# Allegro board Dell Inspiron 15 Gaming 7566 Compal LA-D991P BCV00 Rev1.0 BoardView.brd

Outline 310.04 x 134.8 mm; copper layers: TOP, GND1, IN1, VCC, IN2, IN3, GND2, BOTTOM. Coordinates in mm from the lower left corner of the outline.

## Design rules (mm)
constraint set DEFAULT: min track width 0.102
net group 90H_5.4/8/6.5/6.5/5.4: nets XTAL_OUT XTALIN
net group CLK_PEG_N16P: nets CLK_PEG_N16P CLK_PEG_N16P#
net group CPU_24MHZ_P: nets CPU_24MHZ_N CPU_24MHZ_P
net group DDC_CLK_HDMI: nets DDC_CLK_HDMI DDC_DAT_HDMI
net group DIFFPAIR0: nets VCCSENSE_VGA VSSSENSE_VGA
net group DIFFPAIR1: nets VCCSA_SENSE VSSSA_SENSE
net group DMI_CRX_PTX_0: nets DMI_CRX_PTX_N0 DMI_CRX_PTX_P0
net group DMI_CRX_PTX_1: nets DMI_CRX_PTX_N1 DMI_CRX_PTX_P1
net group DMI_CRX_PTX_2: nets DMI_CRX_PTX_N2 DMI_CRX_PTX_P2
net group DMI_CRX_PTX_3: nets DMI_CRX_PTX_N3 DMI_CRX_PTX_P3
net group DMI_CTX_PRX_0: nets DMI_CTX_PRX_N0 DMI_CTX_PRX_P0
net group DMI_CTX_PRX_1: nets DMI_CTX_PRX_N1 DMI_CTX_PRX_P1
net group DMI_CTX_PRX_2: nets DMI_CTX_PRX_N2 DMI_CTX_PRX_P2
net group DMI_CTX_PRX_3: nets DMI_CTX_PRX_N3 DMI_CTX_PRX_P3
net group DP1: nets N123984002 N123984213
net group DP2: nets N123984081 N123985122
net group DP3: nets N57527 V3N
net group DP4: nets N122477585 V2N
net group DP5: nets N122476680 V1N
net group DP6: nets ISUMN_SA ISUMP_SA
net group DP7: nets VCCIO_SENSE VSSIO_SENSE
net group EDP_AUX: nets EDP_AUXN EDP_AUXP
net group EDP_AUX_C: nets EDP_AUXN_C EDP_AUXP_C
net group EDP_AUX_R: nets EDP_AUXN_R EDP_AUXP_R
net group EDP_TX0: nets EDP_TXN0 EDP_TXP0
net group EDP_TX0_C: nets EDP_TXN0_C EDP_TXP0_C
net group EDP_TX0_R: nets EDP_TXN0_R EDP_TXP0_R
net group EDP_TX1: nets EDP_TXN1 EDP_TXP1
net group EDP_TX1_C: nets EDP_TXN1_C EDP_TXP1_C
net group EDP_TX1_R: nets EDP_TXN1_R EDP_TXP1_R
net group EDP_TX2: nets EDP_TXN2 EDP_TXP2
net group EDP_TX2_C: nets EDP_TXN2_C EDP_TXP2_C
net group EDP_TX2_R: nets EDP_TXN2_R EDP_TXP2_R
net group EDP_TX3: nets EDP_TXN3 EDP_TXP3
net group EDP_TX3_C: nets EDP_TXN3_C EDP_TXP3_C
net group EDP_TX3_R: nets EDP_TXN3_R EDP_TXP3_R
net group FBA_CLK0: nets FBA_CLK0 FBA_CLK0#
net group FBA_CLK1: nets FBA_CLK1 FBA_CLK1#
net group FBA_WCK0: nets FBA_WCK0 FBA_WCK0_N
net group FBA_WCK1: nets FBA_WCK1 FBA_WCK1_N
net group FBA_WCK2: nets FBA_WCK2 FBA_WCK2_N
net group FBA_WCK3: nets FBA_WCK3 FBA_WCK3_N
net group FBC_CLK0: nets FBC_CLK0 FBC_CLK0#
net group FBC_CLK1: nets FBC_CLK1 FBC_CLK1#
net group FBC_WCK0: nets FBC_WCK0 FBC_WCK0_N
net group FBC_WCK1: nets FBC_WCK1 FBC_WCK1_N
net group FBC_WCK2: nets FBC_WCK2 FBC_WCK2_N
net group FBC_WCK3: nets FBC_WCK3 FBC_WCK3_N
net group PBAT_CHG_SMB: nets PBAT_CHG_SMBCLK PBAT_CHG_SMBDAT
net group PCH_CPU_PCIBCLK_: nets PCH_CPU_PCIBCLK_N PCH_CPU_PCIBCLK_P
net group PCIE_PRX_LANTX_3_C: nets PCIE_PRX_LANTX_N3_C PCIE_PRX_LANTX_P3_C
net group PCIE_PRX_LANTX_5: nets PCIE_PRX_LANTX_N5 PCIE_PRX_LANTX_P5
net group PCIE_PRX_SSDTX_10: nets PCIE_PRX_SSDTX_N10 PCIE_PRX_SSDTX_P10
net group PCIE_PRX_SSDTX_11: nets PCIE_PRX_SSDTX_N11 PCIE_PRX_SSDTX_P11
net group PCIE_PRX_SSDTX_12: nets PCIE_PRX_SSDTX_N12 PCIE_PRX_SSDTX_P12
net group PCIE_PRX_WLANTX_6: nets PCIE_PRX_WLANTX_N6 PCIE_PRX_WLANTX_P6
net group PCIE_PTX_LANRX_N5: nets PCIE_PTX_LANRX_N5 PCIE_PTX_LANRX_N5_C
net group PCIE_PTX_LANRX_P5: nets PCIE_PTX_LANRX_P5 PCIE_PTX_LANRX_P5_C
net group PCIE_PTX_SSDRX_10: nets PCIE_PTX_SSDRX_N10 PCIE_PTX_SSDRX_P10
net group PCIE_PTX_SSDRX_10_C: nets PCIE_PTX_SSDRX_N10_C PCIE_PTX_SSDRX_P10_C
net group PCIE_PTX_SSDRX_11: nets PCIE_PTX_SSDRX_N11 PCIE_PTX_SSDRX_P11
net group PCIE_PTX_SSDRX_11_C: nets PCIE_PTX_SSDRX_N11_C PCIE_PTX_SSDRX_P11_C
net group PCIE_PTX_SSDRX_12: nets PCIE_PTX_SSDRX_N12 PCIE_PTX_SSDRX_P12
net group PCIE_PTX_SSDRX_12_C: nets PCIE_PTX_SSDRX_N12_C PCIE_PTX_SSDRX_P12_C
net group PCIE_PTX_WLANRX_6: nets PCIE_PTX_WLANRX_N6 PCIE_PTX_WLANRX_P6
net group PCIE_PTX_WLANRX_RE_6: nets PCIE_PTX_WLANRX_RE_N6 PCIE_PTX_WLANRX_RE_P6
net group PEG_GTX_C_HRX_0: nets PEG_GTX_C_HRX_N0 PEG_GTX_C_HRX_P0
net group PEG_GTX_C_HRX_1: nets PEG_GTX_C_HRX_N1 PEG_GTX_C_HRX_P1
net group PEG_GTX_C_HRX_2: nets PEG_GTX_C_HRX_N2 PEG_GTX_C_HRX_P2
net group PEG_GTX_C_HRX_3: nets PEG_GTX_C_HRX_N3 PEG_GTX_C_HRX_P3
net group PEG_GTX_C_HRX_4: nets PEG_GTX_C_HRX_N4 PEG_GTX_C_HRX_P4
net group PEG_GTX_C_HRX_5: nets PEG_GTX_C_HRX_N5 PEG_GTX_C_HRX_P5
net group PEG_GTX_C_HRX_6: nets PEG_GTX_C_HRX_N6 PEG_GTX_C_HRX_P6
net group PEG_GTX_C_HRX_7: nets PEG_GTX_C_HRX_N7 PEG_GTX_C_HRX_P7
net group PEG_GTX_C_HRX_8: nets PEG_GTX_C_HRX_N8 PEG_GTX_C_HRX_P8
net group PEG_GTX_C_HRX_9: nets PEG_GTX_C_HRX_N9 PEG_GTX_C_HRX_P9
net group PEG_GTX_C_HRX_10: nets PEG_GTX_C_HRX_N10 PEG_GTX_C_HRX_P10
net group PEG_GTX_C_HRX_11: nets PEG_GTX_C_HRX_N11 PEG_GTX_C_HRX_P11
net group PEG_GTX_C_HRX_12: nets PEG_GTX_C_HRX_N12 PEG_GTX_C_HRX_P12
net group PEG_GTX_C_HRX_13: nets PEG_GTX_C_HRX_N13 PEG_GTX_C_HRX_P13
net group PEG_GTX_C_HRX_14: nets PEG_GTX_C_HRX_N14 PEG_GTX_C_HRX_P14
net group PEG_GTX_C_HRX_15: nets PEG_GTX_C_HRX_N15 PEG_GTX_C_HRX_P15
net group PEG_GTX_HRX_0: nets PEG_GTX_HRX_N0 PEG_GTX_HRX_P0
net group PEG_GTX_HRX_1: nets PEG_GTX_HRX_N1 PEG_GTX_HRX_P1
net group PEG_GTX_HRX_2: nets PEG_GTX_HRX_N2 PEG_GTX_HRX_P2
net group PEG_GTX_HRX_3: nets PEG_GTX_HRX_N3 PEG_GTX_HRX_P3
net group PEG_GTX_HRX_4: nets PEG_GTX_HRX_N4 PEG_GTX_HRX_P4
net group PEG_GTX_HRX_5: nets PEG_GTX_HRX_N5 PEG_GTX_HRX_P5
net group PEG_GTX_HRX_6: nets PEG_GTX_HRX_N6 PEG_GTX_HRX_P6
net group PEG_GTX_HRX_7: nets PEG_GTX_HRX_N7 PEG_GTX_HRX_P7
net group PEG_GTX_HRX_8: nets PEG_GTX_HRX_N8 PEG_GTX_HRX_P8
net group PEG_GTX_HRX_9: nets PEG_GTX_HRX_N9 PEG_GTX_HRX_P9
net group PEG_GTX_HRX_10: nets PEG_GTX_HRX_N10 PEG_GTX_HRX_P10
net group PEG_GTX_HRX_11: nets PEG_GTX_HRX_N11 PEG_GTX_HRX_P11
net group PEG_GTX_HRX_12: nets PEG_GTX_HRX_N12 PEG_GTX_HRX_P12
net group PEG_GTX_HRX_13: nets PEG_GTX_HRX_N13 PEG_GTX_HRX_P13
net group PEG_GTX_HRX_14: nets PEG_GTX_HRX_N14 PEG_GTX_HRX_P14
net group PEG_GTX_HRX_15: nets PEG_GTX_HRX_N15 PEG_GTX_HRX_P15
net group PEG_HTX_C_GRX_0: nets PEG_HTX_C_GRX_N0 PEG_HTX_C_GRX_P0
net group PEG_HTX_C_GRX_1: nets PEG_HTX_C_GRX_N1 PEG_HTX_C_GRX_P1
net group PEG_HTX_C_GRX_2: nets PEG_HTX_C_GRX_N2 PEG_HTX_C_GRX_P2
net group PEG_HTX_C_GRX_3: nets PEG_HTX_C_GRX_N3 PEG_HTX_C_GRX_P3
net group PEG_HTX_C_GRX_4: nets PEG_HTX_C_GRX_N4 PEG_HTX_C_GRX_P4
net group PEG_HTX_C_GRX_5: nets PEG_HTX_C_GRX_N5 PEG_HTX_C_GRX_P5
net group PEG_HTX_C_GRX_6: nets PEG_HTX_C_GRX_N6 PEG_HTX_C_GRX_P6
net group PEG_HTX_C_GRX_7: nets PEG_HTX_C_GRX_N7 PEG_HTX_C_GRX_P7
net group PEG_HTX_C_GRX_8: nets PEG_HTX_C_GRX_N8 PEG_HTX_C_GRX_P8
net group PEG_HTX_C_GRX_9: nets PEG_HTX_C_GRX_N9 PEG_HTX_C_GRX_P9
net group PEG_HTX_C_GRX_10: nets PEG_HTX_C_GRX_N10 PEG_HTX_C_GRX_P10
net group PEG_HTX_C_GRX_11: nets PEG_HTX_C_GRX_N11 PEG_HTX_C_GRX_P11
net group PEG_HTX_C_GRX_12: nets PEG_HTX_C_GRX_N12 PEG_HTX_C_GRX_P12
net group PEG_HTX_C_GRX_13: nets PEG_HTX_C_GRX_N13 PEG_HTX_C_GRX_P13
net group PEG_HTX_C_GRX_14: nets PEG_HTX_C_GRX_N14 PEG_HTX_C_GRX_P14
net group PEG_HTX_C_GRX_15: nets PEG_HTX_C_GRX_N15 PEG_HTX_C_GRX_P15
net group PEG_HTX_GRX_0: nets PEG_HTX_GRX_N0 PEG_HTX_GRX_P0
net group PEG_HTX_GRX_1: nets PEG_HTX_GRX_N1 PEG_HTX_GRX_P1
net group PEG_HTX_GRX_2: nets PEG_HTX_GRX_N2 PEG_HTX_GRX_P2
net group PEG_HTX_GRX_3: nets PEG_HTX_GRX_N3 PEG_HTX_GRX_P3
net group PEG_HTX_GRX_4: nets PEG_HTX_GRX_N4 PEG_HTX_GRX_P4
net group PEG_HTX_GRX_5: nets PEG_HTX_GRX_N5 PEG_HTX_GRX_P5
net group PEG_HTX_GRX_6: nets PEG_HTX_GRX_N6 PEG_HTX_GRX_P6
net group PEG_HTX_GRX_7: nets PEG_HTX_GRX_N7 PEG_HTX_GRX_P7
net group PEG_HTX_GRX_8: nets PEG_HTX_GRX_N8 PEG_HTX_GRX_P8
net group PEG_HTX_GRX_9: nets PEG_HTX_GRX_N9 PEG_HTX_GRX_P9
net group PEG_HTX_GRX_10: nets PEG_HTX_GRX_N10 PEG_HTX_GRX_P10
net group PEG_HTX_GRX_11: nets PEG_HTX_GRX_N11 PEG_HTX_GRX_P11
net group PEG_HTX_GRX_12: nets PEG_HTX_GRX_N12 PEG_HTX_GRX_P12
net group PEG_HTX_GRX_13: nets PEG_HTX_GRX_N13 PEG_HTX_GRX_P13
net group PEG_HTX_GRX_14: nets PEG_HTX_GRX_N14 PEG_HTX_GRX_P14
net group PEG_HTX_GRX_15: nets PEG_HTX_GRX_N15 PEG_HTX_GRX_P15
net group REMOTE1: nets REMOTE1+ REMOTE1-
net group REMOTE2: nets REMOTE2+ REMOTE2-
net group SATA_PRX_DTX_1B: nets SATA_PRX_DTX_N1B SATA_PRX_DTX_P1B
net group SATA_PRX_DTX_1B_RC: nets SATA_PRX_DTX_N1B_RC SATA_PRX_DTX_P1B_RC
net group SATA_PRX_SSDTX_0A: nets SATA_PRX_SSDTX_N0A SATA_PRX_SSDTX_P0A
net group SATA_PTX_DRX_1B: nets SATA_PTX_DRX_N1B SATA_PTX_DRX_P1B
net group SATA_PTX_DRX_1B_RC: nets SATA_PTX_DRX_N1B_RC SATA_PTX_DRX_P1B_RC
net group SATA_PTX_SSDRX_0A: nets SATA_PTX_SSDRX_N0A SATA_PTX_SSDRX_P0A
net group SATA_PTX_SSDRX_0A_C: nets SATA_PTX_SSDRX_N0A_C SATA_PTX_SSDRX_P0A_C
net group SMBUS: nets DDI1_DDPB_CTRLDAT I2CB_SDA
net group TMDS_T_TX0P: nets TMDS_T_TX0N TMDS_T_TX0P
net group TMDS_T_TX1P: nets TMDS_T_TX1N TMDS_T_TX1P
net group TMDS_T_TX2P: nets TMDS_T_TX2N TMDS_T_TX2P
net group TMDS_T_TXCP: nets TMDS_T_TXCN TMDS_T_TXCP
net group USB3RN1_D: nets USB3RN1_D- USB3RP1_D+
net group USB3RN2_D: nets USB3RN2_D- USB3RP2_D+
net group USB3T_1: nets USB3T_N1 USB3T_P1
net group USB3T_2: nets USB3T_N2 USB3T_P2
net group USB3TN2_D: nets USB3TN2_D- USB3TP2_D+
net group USB3TP1_D: nets USB3TN1_D- USB3TP1_D+
net group USB20_P3: nets USB20_N3 USB20_P3
net group USB20_P4: nets USB20_N4 USB20_P4
net group USB20_P4_R: nets USB20_N4_R USB20_P4_R
net group USB20_P7: nets USB20_N7 USB20_P7
net group USB20_P9: nets USB20_N9 USB20_P9
net group USB20_P9_R: nets USB20_N9_R USB20_P9_R
net group USB20_P12: nets USB20_N12 USB20_P12
net group USB20_P12_R: nets USB20_N12_R USB20_P12_R
net group XDP: nets XDP_PRDY# XDP_PREQ#
net group 12: nets EC_SPI_CS# EC_SPI_CS#_R EC_SPI_SI EC_SPI_SI_R EC_SPI_SO EC_SPI_SO_R PCH_SPI_HOLD# PCH_SPI_HOLD#_R PCH_SPI_SI PCH_SPI_SI_R PCH_SPI_SO PCH_SPI_SO_R PCH_SPI_WP# PCH_SPI_WP#_R
net group 15: nets HDA_BITCLK HDA_BITCLK_AUDIO USB2_COMP
net group 20: nets DDI1_DDPB_CTRLCLK EC_SPI_CLK EC_SPI_CLK_R GPU_THM_SMBCLK I2C0_SCK I2C1_SCK_TP I2C1_SCK_TP_C I2CB_SCL N120361079 PCH_SMBCLK PCH_SPI_CLK PCH_SPI_CLK_R SMBCLK SML0_SMBCLK SML1_SMBCLK SUSCLK SUSCLK_R VGA_SMB_CK2
net group ASYNCHRONOUS: nets CFG_RCOMP DGPU_HOLD_RST# EDP_COMP H_CATERR# H_CPUPWRGD H_PROCHOT# H_PROCHOT#_R H_THERMTRIP# ME_SUS_PWR_ACK PCH_DPWROK PCH_PLTRST# PCH_PWROK PCH_RSMRST#_R PCH_RTCRST# SYS_PWROK SYS_RESET#
net group CLK_PCIE_SSD: nets CLK_PCIE_SSD
net group CODEC: nets RING2_R
net group DDRA_CLK: nets DDR_A_DQS0 DDR_A_DQS1 DDR_A_DQS2 DDR_A_DQS3 DDR_A_DQS4 DDR_A_DQS5 DDR_A_DQS6 DDR_A_DQS7 M_CLK_DDR0 M_CLK_DDR1 M_CLK_DDR#0 M_CLK_DDR#1
net group DDRA_CMD: nets DDR_A_ACT# DDR_A_ALERT# DDR_A_BG0 DDR_A_BG1 DDR_A_BS0 DDR_A_BS1 DDR_A_CAS# DDR_A_MA0 DDR_A_MA1 DDR_A_MA2 DDR_A_MA3 DDR_A_MA4 DDR_A_MA5 DDR_A_MA6 DDR_A_MA7 DDR_A_MA8 DDR_A_MA9 DDR_A_MA10 DDR_A_MA11 DDR_A_MA12 DDR_A_MA13 DDR_A_PAR DDR_A_RAS# DDR_A_WE#
net group DDRA_CTL: nets DDR_CKE0_DIMMA DDR_CKE1_DIMMA DDR_CS0_DIMMA# DDR_CS1_DIMMA# M_ODT0 M_ODT1
net group DDRA_D0: nets DDR_A_D0 DDR_A_D1 DDR_A_D2 DDR_A_D3 DDR_A_D4 DDR_A_D5 DDR_A_D6 DDR_A_D7 DDR_A_DQS#0
net group DDRA_D1: nets DDR_A_D8 DDR_A_D9 DDR_A_D10 DDR_A_D11 DDR_A_D12 DDR_A_D13 DDR_A_D14 DDR_A_D15 DDR_A_DQS#1
net group DDRA_D2: nets DDR_A_D16 DDR_A_D17 DDR_A_D18 DDR_A_D19 DDR_A_D20 DDR_A_D21 DDR_A_D22 DDR_A_D23 DDR_A_DQS#2
net group DDRA_D3: nets DDR_A_D24 DDR_A_D25 DDR_A_D26 DDR_A_D27 DDR_A_D28 DDR_A_D29 DDR_A_D30 DDR_A_D31 DDR_A_DQS#3
net group DDRA_D4: nets DDR_A_D32 DDR_A_D33 DDR_A_D34 DDR_A_D35 DDR_A_D36 DDR_A_D37 DDR_A_D38 DDR_A_D39 DDR_A_DQS#4
net group DDRA_D5: nets DDR_A_D40 DDR_A_D41 DDR_A_D42 DDR_A_D43 DDR_A_D44 DDR_A_D45 DDR_A_D46 DDR_A_D47 DDR_A_DQS#5
net group DDRA_D6: nets DDR_A_D48 DDR_A_D49 DDR_A_D50 DDR_A_D51 DDR_A_D52 DDR_A_D53 DDR_A_D54 DDR_A_D55 DDR_A_DQS#6
net group DDRA_D7: nets DDR_A_D56 DDR_A_D57 DDR_A_D58 DDR_A_D59 DDR_A_D60 DDR_A_D61 DDR_A_D62 DDR_A_D63 DDR_A_DQS#7
net group DDRB_CLK: nets DDR_B_DQS0 DDR_B_DQS1 DDR_B_DQS2 DDR_B_DQS3 DDR_B_DQS4 DDR_B_DQS5 DDR_B_DQS6 DDR_B_DQS7 M_CLK_DDR2 M_CLK_DDR3 M_CLK_DDR#2 M_CLK_DDR#3
net group DDRB_CMD: nets DDR_B_ACT# DDR_B_ALERT# DDR_B_BG0 DDR_B_BG1 DDR_B_BS0 DDR_B_BS1 DDR_B_CAS# DDR_B_MA0 DDR_B_MA1 DDR_B_MA2 DDR_B_MA3 DDR_B_MA4 DDR_B_MA5 DDR_B_MA6 DDR_B_MA7 DDR_B_MA8 DDR_B_MA9 DDR_B_MA10 DDR_B_MA11 DDR_B_MA12 DDR_B_MA13 DDR_B_PAR DDR_B_RAS# DDR_B_WE#
net group DDRB_CTL: nets DDR_CKE2_DIMMB DDR_CKE3_DIMMB DDR_CS2_DIMMB# DDR_CS3_DIMMB# M_ODT2 M_ODT3
net group DDRB_D0: nets DDR_B_D0 DDR_B_D1 DDR_B_D2 DDR_B_D3 DDR_B_D4 DDR_B_D5 DDR_B_D6 DDR_B_D7 DDR_B_DQS#0
net group DDRB_D1: nets DDR_B_D8 DDR_B_D9 DDR_B_D10 DDR_B_D11 DDR_B_D12 DDR_B_D13 DDR_B_D14 DDR_B_D15 DDR_B_DQS#1
net group DDRB_D2: nets DDR_B_D16 DDR_B_D17 DDR_B_D18 DDR_B_D19 DDR_B_D20 DDR_B_D21 DDR_B_D22 DDR_B_D23 DDR_B_DQS#2
net group DDRB_D3: nets DDR_B_D24 DDR_B_D25 DDR_B_D26 DDR_B_D27 DDR_B_D28 DDR_B_D29 DDR_B_D30 DDR_B_D31 DDR_B_DQS#3
net group DDRB_D4: nets DDR_B_D32 DDR_B_D33 DDR_B_D34 DDR_B_D35 DDR_B_D36 DDR_B_D37 DDR_B_D38 DDR_B_D39 DDR_B_DQS#4
net group DDRB_D5: nets DDR_B_D40 DDR_B_D41 DDR_B_D42 DDR_B_D43 DDR_B_D44 DDR_B_D45 DDR_B_D46 DDR_B_D47 DDR_B_DQS#5
net group DDRB_D6: nets DDR_B_D48 DDR_B_D49 DDR_B_D50 DDR_B_D51 DDR_B_D52 DDR_B_D53 DDR_B_D54 DDR_B_D55 DDR_B_DQS#6
net group DDRB_D7: nets DDR_B_D56 DDR_B_D57 DDR_B_D58 DDR_B_D59 DDR_B_D60 DDR_B_D61 DDR_B_D62 DDR_B_D63 DDR_B_DQS#7
net group DP: nets DDI1_CPU_AUXN DDI1_CPU_AUXN_C DDI1_CPU_AUXP DDI1_CPU_AUXP_C DDI1_HTX_TBRX_N0 DDI1_HTX_TBRX_N0_C DDI1_HTX_TBRX_N1 DDI1_HTX_TBRX_N1_C DDI1_HTX_TBRX_N2 DDI1_HTX_TBRX_N2_C DDI1_HTX_TBRX_N3 DDI1_HTX_TBRX_N3_C DDI1_HTX_TBRX_P0 DDI1_HTX_TBRX_P0_C DDI1_HTX_TBRX_P1 DDI1_HTX_TBRX_P1_C DDI1_HTX_TBRX_P2 DDI1_HTX_TBRX_P2_C DDI1_HTX_TBRX_P3 DDI1_HTX_TBRX_P3_C
net group FBA_CMD: nets FBA_ABI#_H FBA_ABI#_L FBA_CAS#_H FBA_CAS#_L FBA_CKE_H FBA_CKE_L FBA_CS#_H FBA_CS#_L FBA_MA0_MA10_H FBA_MA0_MA10_L FBA_MA1_MA9_H FBA_MA1_MA9_L FBA_MA2_BA0_H FBA_MA2_BA0_L FBA_MA3_BA3_H FBA_MA3_BA3_L FBA_MA4_BA2_H FBA_MA4_BA2_L FBA_MA5_BA1_H FBA_MA5_BA1_L FBA_MA6_MA11_H FBA_MA6_MA11_L FBA_MA7_MA8_H FBA_MA7_MA8_L FBA_MA12_RFU_H FBA_MA12_RFU_L FBA_RAS#_H FBA_RAS#_L FBA_RST#_H FBA_RST#_L FBA_WE#_H FBA_WE#_L
net group FBA_D0: nets FBA_D0 FBA_D1 FBA_D2 FBA_D3 FBA_D4 FBA_D5 FBA_D6 FBA_D7
net group FBA_D1: nets FBA_D8 FBA_D9 FBA_D10 FBA_D11 FBA_D12 FBA_D13 FBA_D14 FBA_D15
net group FBA_D2: nets FBA_D16 FBA_D17 FBA_D18 FBA_D19 FBA_D20 FBA_D21 FBA_D22 FBA_D23
net group FBA_D3: nets FBA_D24 FBA_D25 FBA_D26 FBA_D27 FBA_D28 FBA_D29 FBA_D30 FBA_D31
net group FBA_D4: nets FBA_D32 FBA_D33 FBA_D34 FBA_D35 FBA_D36 FBA_D37 FBA_D38 FBA_D39
net group FBA_D5: nets FBA_D40 FBA_D41 FBA_D42 FBA_D43 FBA_D44 FBA_D45 FBA_D46 FBA_D47
net group FBA_D6: nets FBA_D48 FBA_D49 FBA_D50 FBA_D51 FBA_D52 FBA_D53 FBA_D54 FBA_D55
net group FBA_D7: nets FBA_D56 FBA_D57 FBA_D58 FBA_D59 FBA_D60 FBA_D61 FBA_D62 FBA_D63
net group FBA_DBI: nets FBA_DBI0# FBA_DBI1# FBA_DBI2# FBA_DBI3# FBA_DBI4# FBA_DBI5# FBA_DBI6# FBA_DBI7#
net group FBA_EDC: nets FBA_EDC0 FBA_EDC1 FBA_EDC2 FBA_EDC3 FBA_EDC4 FBA_EDC5 FBA_EDC6 FBA_EDC7
net group FBC_CMD: nets FBC_ABI#_H FBC_ABI#_L FBC_CAS#_H FBC_CAS#_L FBC_CKE_H FBC_CKE_L FBC_CS#_H FBC_CS#_L FBC_MA0_MA10_H FBC_MA0_MA10_L FBC_MA1_MA9_H FBC_MA1_MA9_L FBC_MA2_BA0_H FBC_MA2_BA0_L FBC_MA3_BA3_H FBC_MA3_BA3_L FBC_MA4_BA2_H FBC_MA4_BA2_L FBC_MA5_BA1_H FBC_MA5_BA1_L FBC_MA6_MA11_H FBC_MA6_MA11_L FBC_MA7_MA8_H FBC_MA7_MA8_L FBC_MA12_RFU_H FBC_MA12_RFU_L FBC_RAS#_H FBC_RAS#_L FBC_RST#_H FBC_RST#_L FBC_WE#_H FBC_WE#_L
net group FBC_D0: nets FBC_D0 FBC_D1 FBC_D2 FBC_D3 FBC_D4 FBC_D5 FBC_D6 FBC_D7
net group FBC_D1: nets FBC_D8 FBC_D9 FBC_D10 FBC_D11 FBC_D12 FBC_D13 FBC_D14 FBC_D15
net group FBC_D2: nets FBC_D16 FBC_D17 FBC_D18 FBC_D19 FBC_D20 FBC_D21 FBC_D22 FBC_D23
net group FBC_D3: nets FBC_D24 FBC_D25 FBC_D26 FBC_D27 FBC_D28 FBC_D29 FBC_D30 FBC_D31
net group FBC_D4: nets FBC_D32 FBC_D33 FBC_D34 FBC_D35 FBC_D36 FBC_D37 FBC_D38 FBC_D39
net group FBC_D5: nets FBC_D40 FBC_D41 FBC_D42 FBC_D43 FBC_D44 FBC_D45 FBC_D46 FBC_D47
net group FBC_D6: nets FBC_D48 FBC_D49 FBC_D50 FBC_D51 FBC_D52 FBC_D53 FBC_D54 FBC_D55
net group FBC_D7: nets FBC_D56 FBC_D57 FBC_D58 FBC_D59 FBC_D60 FBC_D61 FBC_D62 FBC_D63
net group FBC_DBI: nets FBC_DBI0# FBC_DBI1# FBC_DBI2# FBC_DBI3# FBC_DBI4# FBC_DBI5# FBC_DBI6# FBC_DBI7#
net group FBC_EDC: nets FBC_EDC0 FBC_EDC1 FBC_EDC2 FBC_EDC3 FBC_EDC4 FBC_EDC5 FBC_EDC6 FBC_EDC7
net group GPU_THM_SMBCLK: nets GPU_THM_SMBDAT
net group HDA: nets HDA_CODEC_SDIN0 HDA_SDIN0 HDA_SDIN0_AUDIO HDA_SDOUT HDA_SDOUT_AUDIO HDA_SYNC HDA_SYNC_AUDIO
net group I2C0_SCK: nets I2C0_SDA
net group I2C1_SCK_TP: nets I2C1_SDA_TP
net group I2C1_SCK_TP_C: nets I2C1_SDA_TP_C
net group LAD-S30/30: nets MDI0+ MDI0- MDI1+ MDI1- MDI2+ MDI2- MDI3+ MDI3- MDO0+ MDO0- MDO1+ MDO1- MDO2+ MDO2- MDO3+ MDO3-
net group LPC-15: nets LPC_LAD0 LPC_LAD1 LPC_LAD2 LPC_LAD3 LPC_LFRAME#
net group PCH_SMBCLK: nets PCH_SMBDATA
net group PECI: nets PECI_EC
net group PLATFORM_CLK: nets CLK_PCIE_LAN CLK_PCIE_LAN# CLK_PCIE_SSD# CLK_PCIE_WLAN CLK_PCIE_WLAN# PCH_CPU_BCLK_N PCH_CPU_BCLK_P PEX_TSTCLK_OUT PEX_TSTCLK_OUT#
net group PWN: nets +VCCSTG
net group REF V/G: nets CFG0 CFG2 CFG4 CFG5 CFG6 CFG7 PCH_JTAG_TCK PCH_JTAG_TDI PCH_JTAG_TDO PCH_JTAG_TMS PCIE_WAKE# RUNPWROK SIO_SLP_S0# SIO_SLP_S3# SIO_SLP_S4# SIO_SLP_S5# VR_ON
net group SIN_CLK: nets AUD_AZA_CPU_SCLK AUD_AZA_CPU_SCLK_R CLK_PCI_LPC_MEC LAN_CLKREQ# SRCCLKREQ1# SRCCLKREQ4# SRCCLKREQ5# SRCCLKREQ8# SRCCLKREQ9# SRCCLKREQ10# SRCCLKREQ11# SRCCLKREQ13# SRCCLKREQ14# SRCCLKREQ15# SSD_CLK_REQ# VGA_CLK_REQ# WLAN_CLK_REQ#
net group SMBCLK: nets SMBDATA
net group SML0_SMBCLK: nets SML0_SMBDATA
net group SML1_SMBCLK: nets SML1_SMBDAT
net group SPACING-10: nets FCCM_GT FCCM_SA FCCM_VCORE N121479122 N121710332 N121712022 N122314333 PWM1_GT PWM1_VCORE PWM2_VCORE PWM3_VCORE PWM_SA VCC_SENSE VCCGT_SENSE VSS_SENSE VSSGT_SENSE
net group SPK: nets AUD_SPK_L+ AUD_SPK_L+_C AUD_SPK_L- AUD_SPK_L-_C AUD_SPK_R+ AUD_SPK_R+_C AUD_SPK_R- AUD_SPK_R-_C
net group SVID: nets VR_SVID_ALERT# VR_SVID_ALERT#_C VR_SVID_ALERT#_R VR_SVID_CLK VR_SVID_CLK_C VR_SVID_DATA VR_SVID_DATA_C
net group USB2.0: nets USB20_N1 USB20_N2 USB20_P1 USB20_P2 USBP1_R_D+ USBP1_R_D- USBP2_D+ USBP2_D- USBP2_R_D+ USBP2_R_D-
net group USB3.0: nets USB3RN1 USB3RN2 USB3RN3 USB3RP1 USB3RP2 USB3RP3 USB3TN1 USB3TN2 USB3TN3 USB3TP1 USB3TP2 USB3TP3
net group VGA_SMB_CK2: nets VGA_SMB_DA2
nets with their own width: min track width 0.127; nets PCH_RTCX1 PCH_RTCX2 XTAL24_IN XTAL24_OUT XTALSSIN XTLI XTLO
nets with their own width: min track width 0.254; nets +3V_ROM +3VS_TP
nets with their own width: min track width 0.305; nets PCIE_RCOMPN PCIE_RCOMPP
nets with their own width: min track width 0.406; nets +FBA_VREFD_L
nets with their own width: min track width 0.508; nets 5VS_FAN1 5VS_FAN2 +0.95VSP +1.2V_DDR +1.2V_VCCPLL_OC +1.35VS_VGA +1V_MPHY_MPHYPLL +1V_PCH +1V_PCH_AZPLL +1V_PCH_CLK5 +1V_PCH_PRIM +1V_PCH_USBPLL +1VALW +3V_PCH_AZIO +3V_PCH_DSW +3VALW_EC +3VLP +3VS +5V_AVDD +5V_CHGUSB_2 +5VALW +5VS +5VS_KBL +19VB_1VALWP +CHGRTC +GPU_CORE +PLLVDD +RTCBATT +RTCVCC +RTCVCC_VBAT +V_DAC +V_DDR_REFA +V_DDR_REFA_R +V_DDR_REFB +V_DDR_REFB_R +VCC_CORE +VCCSA +VGA_B+ AUD_AGND B+ BATT++ DTH_VDD12 EC_AGND GND GVDD N18094620 N128731318 VCCGT_B+ VCORE_B+ VIN
nets with their own width: min track width 0.762; nets +1.8V_AVDD +1.8V_DVDD +1.8VS +1V_VCCDSW +3V_DVDD +3VS_CAM +3VS_WLAN
nets with their own width: min track width 1.016; nets +0.6VS +0.6VSP +1.2V_DTH +3V_PCH_SPI +3VS_DTH +VDISPLAY_VCC DTH_VDD33 DTH_VDDA12 DTH_VDDRX12 DTH_VDDTX12 RING2 SLEEVE SLEEVE_R
nets with their own width: min track width 1.524; nets +1V_MPHY +5VS_HDD +EDPVDD +INV_PWR_SRC +LAN_IO +LAN_VDD
nets with their own width: min track width 2.032; nets +5V_CHGUSB_1 +5V_PVDD
nets with their own width: min track width 3.048; nets +3.3VDX_SSD

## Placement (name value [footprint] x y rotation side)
CA1  4.7U_0603_6.3V6K  [C_0603]  288.17 27.49 0 top
CA2  0.1U_0402_10V6K  [C_0402]  288.41 28.57 0 top
CA3  0.1U_0402_10V6K  [C_0402]  285.63 28.57 0 top
CA4  1U_0402_6.3V6K  [C_0402]  289.95 37.35 0 top
CA7  1U_0402_6.3V6K  [C_0402]  288.93 31.69 0 top
CA8  4.7U_0603_6.3V6K  [C_0603]  275.66 20.82 180 top
CA9  0.1U_0402_10V6K  [C_0402]  275.42 21.96 180 top
CA10  0.68U_0603_16V6K  [C_0603]  289.06 37.33 180 top
CA11  10U_0603_6.3V6M~D  [C_0603]  278.33 30.98 90 top
CA12  0.1U_0402_10V6K  [C_0402]  279.41 30.9 90 top
CA13  10U_0603_6.3V6M~D  [C_0603]  280.49 30.98 90 top
CA14  0.1U_0402_10V6K  [C_0402]  281.57 30.9 90 top
CA15  1U_0402_6.3V6K  [C_0402]  286.55 27.68 180 top
CA16  2.2U_0402_6.3V6M  [C_0402]  287.97 23.64 180 top
CA17  0.1U_0402_10V6K  [C_0402]  284.52 20.13 270 top
CA18  4.7U_0603_6.3V6K  [C_0603]  286.24 20.49 0 top
CA19  4.7U_0603_6.3V6K  [C_0603]  288.3 22.57 180 top
CA20  1U_0402_6.3V6K  [C_0402]  285.63 28.45 270 bottom
CA21  1U_0402_6.3V6K  [C_0402]  283.63 20.13 270 top
CA22  10U_0603_6.3V6M  [C_0603]  284.49 29.64 180 bottom
CA23  10U_0603_6.3V6M  [C_0603]  281.63 21.58 180 bottom
CA24  0.1U_0402_10V6K  [C_0402]  278.47 20.06 180 top
CA25  4.7U_0603_6.3V6K  [C_0603]  275.66 19.55 180 top
CA26  0.1U_0402_10V6K  [C_0402]  275.42 27.55 180 top
CA27  4.7U_0603_6.3V6K  [C_0603]  275.92 24.88 180 top
CA28  0.1U_0402_10V6K  [C_0402]  275.42 22.85 180 top
CA29  0.1U_0402_10V6K  [C_0402]  279.83 17.45 90 top
CA30  22P_0402_50V8J  [C_0402]  272.22 25.45 0 top
CA31  .1U_0402_16V7K  [C_0402]  273.64 25.9 180 bottom
CA32  .1U_0402_16V7K  [C_0402]  275.41 23.92 90 bottom
CA33  33P_0402_50V8J  [C_0402]  272.68 24.04 90 bottom
CA34  0.01U_0201_16V7  [C_0201]  270.52 22.3 90 top
CA35  0.01U_0201_16V7  [C_0201]  273.25 22.68 90 top
CA36  1000P_0402_50V7K  [C_0402]  278.06 15.66 180 top
CA37  1000P_0402_50V7K  [C_0402]  275.37 15.66 0 top
CA38  1000P_0402_50V7K  [C_0402]  273.24 15.66 180 top
CA39  1000P_0402_50V7K  [C_0402]  270.55 15.66 0 top
CA40  100P_0402_50V8J  [C_0402]  292.57 18.05 180 top
CA41  100P_0402_50V8J  [C_0402]  296.48 16.78 0 top
CA42  100P_0402_50V8J  [C_0402]  296.99 12.06 0 bottom
CA43  100P_0402_50V8J  [C_0402]  293.25 18.23 270 bottom
CA44  680P_0402_50V7K  [C_0402]  259.67 10.89 180 bottom
CA45  680P_0402_50V7K  [C_0402]  261.96 10.71 0 bottom
CA46  330P_0402_50V7K  [C_0402]  257.92 14.67 0 bottom
CA47  330P_0402_50V7K  [C_0402]  268.26 15.2 0 bottom
CA48  0.22U_0603_50V7K  [C_0603]  258.99 16.98 270 bottom
CA49  0.22U_0603_50V7K  [C_0603]  261.25 14.77 0 bottom
CA50  0.22U_0603_50V7K  [C_0603]  264.42 14.62 0 bottom
CA51  0.22U_0603_50V7K  [C_0603]  268.08 16.14 90 bottom
CA52  1000P_0402_50V7K  [C_0402]  258.79 18.79 180 bottom
CA53  10U_0603_25V6M  [C_0603]  258.85 19.83 180 bottom
CA54  1000P_0402_50V7K  [C_0402]  269.5 18.84 90 top
CA55  0.1U_0402_25V6  [C_0402]  271.79 18.84 90 top
CA56  10U_0603_25V6M  [C_0603]  270.65 18.85 90 top
CA57  0.1U_0402_25V6  [C_0402]  258.79 17.9 180 bottom
CA60  680P_0402_50V7K  [C_0402]  296.93 9.46 225 bottom
CA61  680P_0402_50V7K  [C_0402]  294.14 18.23 270 bottom
CA62  10P_0402_25V8J  [C_0402]  275.42 26.66 180 top
CA63  10U_0603_6.3V6M  [C_0603]  284.49 29.64 180 top
CA64  10U_0603_6.3V6M~D  [C_0603]  295.41 15.55 270 top
CA65  10U_0603_6.3V6M~D  [C_0603]  294.14 15.55 270 top
CA66  1U_0603_25V6  [C_0603]  253.06 24.63 0 bottom
CA67  0.1U_0402_25V6  [C_0402]  255.2 29.45 0 bottom
CC4  12P_0402_50V8J  [C_0402]  170.7 15.41 90 top
CC5  12P_0402_50V8J  [C_0402]  184.81 24.29 0 top
CC27  1U_0402_6.3V6K  [C_0402]  154.51 18.8 270 bottom
CC298  0.1U_0402_16V7K  [C_0402]  131.66 75.43 180 top
CD1  1U_0402_6.3V6K  [C_0402]  96.61 42.79 180 top
CD2  1U_0402_6.3V6K  [C_0402]  79.85 43.03 0 top
CD3  1U_0402_6.3V6K  [C_0402]  138.65 41.12 0 top
CD4  1U_0402_6.3V6K  [C_0402]  138.65 40.24 0 top
CD5  10U_0603_6.3V6M  [C_0603]  112.62 44.43 0 top
CD6  10U_0603_6.3V6M  [C_0603]  102.05 44.44 0 top
CD7  10U_0603_6.3V6M  [C_0603]  131.9 43.81 180 top
CD8  10U_0603_6.3V6M  [C_0603]  89.76 44.05 180 top
CD9  10U_0603_6.3V6M  [C_0603]  138.5 39.11 180 top
CD10  10U_0603_6.3V6M  [C_0603]  139.52 39.11 0 top
CD11  330U_X_2VM_R6M  [C_X]  91.53 15.48 180 bottom
CD12  1U_0402_6.3V6K  [C_0402]  138.11 31.23 0 top
CD13  10U_0603_6.3V6M  [C_0603]  136.6 29.96 180 top
CD14  10U_0603_6.3V6M  [C_0603]  136.6 31.23 180 top
CD15  10U_0603_6.3V6M  [C_0603]  138.12 29.96 0 top
CD16  0.1U_0402_10V6K  [C_0402]  135.8 43.08 90 top
CD17  2.2U_0402_6.3V6M  [C_0402]  134.91 43.08 90 top
CD19  1U_0402_6.3V6K  [C_0402]  94.42 19.55 0 top
CD20  1U_0402_6.3V6K  [C_0402]  83.88 19.68 0 top
CD21  1U_0402_6.3V6K  [C_0402]  102.71 19.52 0 top
CD22  1U_0402_6.3V6K  [C_0402]  109.41 18 180 top
CD23  10U_0603_6.3V6M  [C_0603]  121.39 28.41 180 top
CD24  10U_0603_6.3V6M  [C_0603]  132.69 28.54 180 top
CD25  10U_0603_6.3V6M  [C_0603]  116.82 19.78 0 top
CD26  10U_0603_6.3V6M  [C_0603]  104.34 28.57 0 top
CD27  10U_0603_6.3V6M  [C_0603]  141.55 26.47 270 top
CD28  10U_0603_6.3V6M  [C_0603]  140.34 26.47 270 top
CD29  0.1U_0402_10V6K  [C_0402]  113.31 21.72 90 top
CD30  1U_0402_6.3V6K  [C_0402]  138.69 27.6 90 top
CD31  1U_0402_6.3V6K  [C_0402]  139.58 27.6 90 top
CD32  1U_0402_6.3V6K  [C_0402]  137.12 20.44 180 top
CD33  330U_2.5V_M  [C_APXK2R5ARA331MF451]  145.93 31.74 180 bottom
CD34  0.1U_0402_10V6K  [C_0402]  136.28 27.6 90 top
CD35  2.2U_0402_6.3V6M  [C_0402]  135.39 27.6 90 top
CD36  4.7U_0603_6.3V6K  [C_0603]  217.92 35.91 0 bottom
CD37  0.22U_0402_10V6K  [C_0402]  205.11 35.91 270 bottom
CD38  0.1U_0402_10V6K  [C_0402]  217.58 19.42 0 bottom
CD39  0.01U_0402_16V7K  [C_0402]  218.21 33.01 0 bottom
CD40  47P_0402_50V8J  [C_0402]  217.58 18.53 0 bottom
CD41  15P_0402_50V8J  [C_0402]  218.19 34.33 0 bottom
CD42  0.22U_0402_10V6K  [C_0402]  204.23 35.91 270 bottom
CD43  0.22U_0402_10V6K  [C_0402]  203.21 35.91 270 bottom
CD44  0.22U_0402_10V6K  [C_0402]  202.32 35.91 270 bottom
CD45  0.22U_0402_10V6K  [C_0402]  201.3 35.91 270 bottom
CD46  0.22U_0402_10V6K  [C_0402]  200.42 35.91 270 bottom
CD51  0.22U_0402_10V6K  [C_0402]  198.51 35.91 270 bottom
CD53  0.22U_0402_10V6K  [C_0402]  199.4 35.91 270 bottom
CD69  .1U_0402_16V7K  [C_0402]  96 16.63 90 bottom
CD70  10U_0603_6.3V6M  [C_0603]  123.17 43.28 0 top
CD71  10U_0603_6.3V6M  [C_0603]  116.94 32.49 0 top
CD72  10U_0603_6.3V6M  [C_0603]  99.86 32.43 90 top
CD73  10U_0603_6.3V6M  [C_0603]  96.75 43.92 180 top
CD74  1U_0402_6.3V6K  [C_0402]  84.06 32.36 180 top
CD75  1U_0402_6.3V6K  [C_0402]  94.7 32.5 180 top
CD76  1U_0402_6.3V6K  [C_0402]  127.62 32.23 180 top
CD77  1U_0402_6.3V6K  [C_0402]  102.04 43.3 0 top
CD78  1U_0402_6.3V6K  [C_0402]  106.34 32.41 90 top
CD79  1U_0402_6.3V6K  [C_0402]  112.61 43.28 0 top
CD80  1U_0402_6.3V6K  [C_0402]  98.39 19.52 0 top
CD81  1U_0402_6.3V6K  [C_0402]  127.34 19.52 0 top
CD82  1U_0402_6.3V6K  [C_0402]  104.61 19.52 0 top
CD83  1U_0402_6.3V6K  [C_0402]  100.42 19.52 0 top
CD84  10U_0603_6.3V6M  [C_0603]  113.13 28.54 0 top
CD85  10U_0603_6.3V6M  [C_0603]  98.15 28.41 180 top
CD86  10U_0603_6.3V6M  [C_0603]  87.83 30.47 180 top
CD87  10U_0603_6.3V6M  [C_0603]  73.35 19.8 180 top
CD88  10U_0603_6.3V6M  [C_0603]  138.25 20.56 0 top
CD89  10U_0603_6.3V6M  [C_0603]  138.25 19.29 0 top
CD90  10U_0603_6.3V6M  [C_0603]  137.23 19.29 180 top
CD91  1U_0402_6.3V6K  [C_0402]  258.76 21.78 180 bottom
CD92  1U_0402_6.3V6K  [C_0402]  258.84 22.72 90 bottom
CD93  1U_0402_6.3V6K  [C_0402]  260.94 22.98 180 bottom
CD94  1U_0402_6.3V6K  [C_0402]  263.66 23.03 90 bottom
CD95  1U_0402_6.3V6K  [C_0402]  264.55 23.03 90 bottom
CD96  0.1U_0402_10V6K  [C_0402]  114.18 32.3 90 top
CE1  0.1U_0402_10V7K~D  [C_0402]  213.24 34.33 90 top
CE2  0.1U_0402_10V6K  [C_0402]  133.36 14.93 270 top
CE4  1U_0402_6.3V6K  [C_0402]  122.54 14.85 270 top
CE5  1U_0402_6.3V6K  [C_0402]  125.77 14.85 270 top
CE6  10U_0603_6.3V6M~D  [C_0603]  123.44 14.65 0 top
CE8  0.047U_0402_16V4Z  [C_0402]  240.85 27.55 0 top
CE9  22P_0402_50V8J  [C_0402]  146.62 14.53 0 bottom
CE10  22P_0402_50V8J  [C_0402]  145.69 14.53 180 bottom
CE12  1U_0402_6.3V6K  [C_0402]  222.64 29.66 270 bottom
CE62  0.1U_0402_10V6K  [C_0402]  236.31 24.88 180 bottom
CE63  1000P_0402_50V7K  [C_0402]  231.78 35.37 270 top
CE64  1000P_0402_50V7K  [C_0402]  239.74 17.64 180 top
CE65  0.1U_0402_10V6K  [C_0402]  217.13 21.58 180 top
CE66  0.1U_0402_10V6K  [C_0402]  226.96 29.66 270 bottom
CE67  0.1U_0402_10V6K  [C_0402]  226.07 16.58 270 bottom
CE68  0.1U_0402_10V6K  [C_0402]  235.93 17.64 180 bottom
CE69  0.1U_0402_10V6K  [C_0402]  220.74 28.74 90 bottom
CE71  0.1U_0402_10V6K  [C_0402]  229.75 15.66 90 bottom
CE72  0.047U_0402_10V7K~D  [C_0402]  230.64 15.66 90 bottom
CE73  0.1U_0402_10V6K  [C_0402]  224.29 34.46 90 bottom
CE74  0.1U_0402_10V6K  [C_0402]  217.13 20.69 180 top
CE76  100P_0402_50V8J  [C_0402]  235.98 34.46 90 top
CE77  0.1U_0402_10V6K  [C_0402]  236.05 29.58 180 bottom
CE78  4.7P_0402_50V8C  [C_0402]  229.68 13.66 180 top
CE79  0.1U_0402_10V6K  [C_0402]  221.14 22.49 90 bottom
CE80  22P_0402_50V8J  [C_0402]  150.7 15.05 270 bottom
CE81  0.1U_0402_10V6K  [C_0402]  228.86 26.58 90 bottom
CE82  1000P_0402_50V7K  [C_0402]  232.88 20.95 180 bottom
CE84  100P_0402_50V8J  [C_0402]  221.62 32.07 270 bottom
CE85  0.1U_0402_10V6K  [C_0402]  236.31 27.55 180 bottom
CE86  47P_0402_50V8J  [C_0402]  236.31 25.77 180 bottom
CE87  2200P_0402_25V7K  [C_0402]  231.66 27.5 270 bottom
CE89  10U_0603_6.3V6M  [C_0603]  238.58 18.79 0 top
CE91  0.1U_0402_10V6K  [C_0402]  223.42 22.72 180 bottom
CE98  0.1U_0402_10V6K  [C_0402]  228.8 29.66 270 bottom
CE99  0.01U_0402_16V7K  [C_0402]  52.97 31.03 90 top
CE100  0.01U_0402_16V7K  [C_0402]  242.28 38.09 180 top
CE101  10P_0402_25V8J  [C_0402]  221.7 35.42 180 top
CE102  10P_0402_25V8J  [C_0402]  222.69 35.42 0 top
CE103  1U_0603_25V6  [C_0603]  217.12 22.72 180 top
CE104  0.1U_0402_10V6K  [C_0402]  227.47 33.82 90 bottom
CH5  0.22U_0201_6.3V6M  [C_0201]  134.63 92.75 0 bottom
CH6  0.22U_0201_6.3V6M  [C_0201]  134.63 93.39 0 bottom
CH7  0.22U_0201_6.3V6M  [C_0201]  136.15 91.73 0 bottom
CH8  0.22U_0201_6.3V6M  [C_0201]  136.15 92.37 0 bottom
CH9  0.22U_0201_6.3V6M  [C_0201]  134.63 90.72 0 bottom
CH10  0.22U_0201_6.3V6M  [C_0201]  134.63 91.35 0 bottom
CH11  0.22U_0201_6.3V6M  [C_0201]  136.15 90.34 0 bottom
CH12  0.22U_0201_6.3V6M  [C_0201]  136.15 89.7 0 bottom
CH13  0.22U_0201_6.3V6M  [C_0201]  134.63 88.69 0 bottom
CH14  0.22U_0201_6.3V6M  [C_0201]  134.63 89.32 0 bottom
CH15  0.22U_0201_6.3V6M  [C_0201]  136.15 88.31 0 bottom
CH16  0.22U_0201_6.3V6M  [C_0201]  136.15 87.67 0 bottom
CH17  0.22U_0201_6.3V6M  [C_0201]  134.63 86.65 0 bottom
CH18  0.22U_0201_6.3V6M  [C_0201]  134.63 87.29 0 bottom
CH19  0.22U_0201_6.3V6M  [C_0201]  136.15 85.64 0 bottom
CH20  0.22U_0201_6.3V6M  [C_0201]  136.15 86.27 0 bottom
CH21  0.22U_0201_6.3V6M  [C_0201]  134.63 85.26 0 bottom
CH22  0.22U_0201_6.3V6M  [C_0201]  134.63 84.62 0 bottom
CH23  0.22U_0201_6.3V6M  [C_0201]  136.15 83.61 0 bottom
CH24  0.22U_0201_6.3V6M  [C_0201]  136.15 84.24 0 bottom
CH25  0.22U_0201_6.3V6M  [C_0201]  134.63 83.23 0 bottom
CH26  0.22U_0201_6.3V6M  [C_0201]  134.63 82.59 0 bottom
CH27  0.22U_0201_6.3V6M  [C_0201]  136.15 81.57 0 bottom
CH28  0.22U_0201_6.3V6M  [C_0201]  136.15 82.21 0 bottom
CH29  0.22U_0201_6.3V6M  [C_0201]  134.63 81.19 0 bottom
CH30  0.22U_0201_6.3V6M  [C_0201]  134.63 80.56 0 bottom
CH31  0.22U_0201_6.3V6M  [C_0201]  136.15 79.54 0 bottom
CH32  0.22U_0201_6.3V6M  [C_0201]  136.15 80.18 0 bottom
CH33  0.22U_0201_6.3V6M  [C_0201]  134.63 79.16 0 bottom
CH34  0.22U_0201_6.3V6M  [C_0201]  134.63 78.53 0 bottom
CH35  0.22U_0201_6.3V6M  [C_0201]  136.15 77.51 0 bottom
CH36  0.22U_0201_6.3V6M  [C_0201]  136.15 78.15 0 bottom
CH45  8.2P_0402_50V8D  [C_0402]  175.48 18.07 0 bottom
CH46  8.2P_0402_50V8D  [C_0402]  174.62 18.07 180 bottom
CH47  15P_0402_50V8J  [C_0402]  182.89 45 90 bottom
CH48  18P_0402_50V8J  [C_0402]  182.89 44.14 270 bottom
CH50  10P_0402_25V8J  [C_0402]  179.38 18.79 0 bottom
CH51  10P_0402_25V8J  [C_0402]  175.29 25.43 0 top
CH52  1U_0402_6.3V6K  [C_0402]  174.61 22.85 180 top
CH53  1U_0402_6.3V6K  [C_0402]  174.38 19.68 270 top
CH70  0.1U_0402_10V6K  [C_0402]  165.74 23.05 270 top
CH80  1U_0402_6.3V6K  [C_0402]  168.6 25.76 90 top
CH82  1U_0402_6.3V6K  [C_0402]  172.22 34.66 90 top
CH100  0.022U_0402_16V7K  [C_0402]  111.92 24.22 0 top
CH101  0.022U_0402_16V7K  [C_0402]  69.91 44.92 0 top
CH102  10U_0603_6.3V6M  [C_0603]  123.23 85.02 90 top
CH103  10U_0603_6.3V6M  [C_0603]  123.2 87.68 90 top
CH104  10U_0603_6.3V6M  [C_0603]  123.19 91.57 270 top
CH106  1U_0402_6.3V6K  [C_0402]  125.04 96.44 0 top
CH110  1U_0402_6.3V6K  [C_0402]  123.13 92.71 0 top
CH111  10U_0603_6.3V6M  [C_0603]  120.31 96.12 270 top
CH112  10U_0603_6.3V6M  [C_0603]  121.76 85.28 180 top
CH113  10U_0603_6.3V6M  [C_0603]  123.97 97.65 0 top
CH114  10U_0603_6.3V6M  [C_0603]  121.76 86.58 180 top
CH115  10U_0603_6.3V6M  [C_0603]  120.48 98.99 90 top
CH116  10U_0603_6.3V6M  [C_0603]  123.97 98.87 0 top
CH117  10U_0603_6.3V6M  [C_0603]  124.15 100.09 0 top
CH118  10U_0603_6.3V6M  [C_0603]  101.24 80.62 90 top
CH119  10U_0603_6.3V6M  [C_0603]  106 80.42 90 top
CH120  10U_0603_6.3V6M  [C_0603]  102.88 76.63 270 top
CH121  10U_0603_6.3V6M  [C_0603]  99.25 78.51 0 top
CH122  10U_0603_6.3V6M  [C_0603]  107.72 79.99 90 top
CH123  10U_0603_6.3V6M  [C_0603]  113.87 76.57 180 top
CH124  10U_0603_6.3V6M  [C_0603]  99.59 80.62 90 top
CH125  10U_0603_6.3V6M  [C_0603]  111.35 79.32 90 top
CH126  10U_0603_6.3V6M  [C_0603]  117.99 76.63 270 top
CH127  10U_0603_6.3V6M  [C_0603]  121.74 81.4 180 top
CH128  10U_0603_6.3V6M  [C_0603]  123.22 76.55 0 top
CH129  22U_0603_6.3V6M  [C_0603]  124.66 60.7 0 top
CH130  22U_0603_6.3V6M  [C_0603]  124.66 59.3 0 top
CH131  22U_0603_6.3V6M  [C_0603]  124.66 57.9 0 top
CH132  22U_0603_6.3V6M  [C_0603]  124.66 56.51 0 top
CH133  1U_0402_6.3V6K  [C_0402]  122.93 99.89 90 top
CH134  1U_0402_6.3V6K  [C_0402]  121.07 101.32 180 top
CH135  1U_0402_6.3V6K  [C_0402]  120.69 98.08 180 top
CH136  47U_0603_6.3V6M  [C_0603]  121.65 92.24 180 top
CH173  0.1U_0402_10V6K  [C_0402]  167.71 25.76 90 top
CH176  1U_0402_6.3V6K  [C_0402]  165.11 24.68 90 top
CH177  22U_0603_6.3V6M  [C_0603]  183.7 38.39 90 bottom
CH178  22U_0603_6.3V6M  [C_0603]  182.48 38.39 90 bottom
CH179  1U_0402_6.3V6K  [C_0402]  181.01 38.09 270 bottom
CH180  1U_0402_6.3V6K  [C_0402]  155.66 42.79 180 top
CH181  22U_0603_6.3V6M  [C_0603]  157.81 45.76 180 top
CH182  22U_0603_6.3V6M  [C_0603]  155.39 45.76 180 top
CH183  1U_0402_6.3V6K  [C_0402]  165.98 36.23 180 top
CH184  10U_0402_6.3V6M  [C_0402]  167.27 37.12 90 top
CH185  10U_0402_6.3V6M  [C_0402]  166.38 37.12 90 top
CH186  0.1U_0402_10V6K  [C_0402]  170.85 24.32 90 top
CH187  1U_0402_6.3V6K  [C_0402]  178.71 21.57 0 top
CH188  1U_0402_6.3V6K  [C_0402]  173.19 32.23 0 top
CH189  0.1U_0402_10V7K  [C_0402]  175.73 26.53 180 top
CH190  0.1U_0402_10V7K  [C_0402]  159 32.36 180 top
CH191  0.1U_0402_10V7K  [C_0402]  158.84 28.82 180 top
CH192  0.1U_0402_10V7K  [C_0402]  155.9 22.99 270 top
CH197  0.1U_0402_10V7K  [C_0402]  81.4 83.1 180 bottom
CH200  0.1U_0402_10V6K  [C_0402]  171.97 25.19 90 top
CH201  22U_0603_6.3V6M  [C_0603]  177.81 28.69 90 top
CH202  22U_0603_6.3V6M  [C_0603]  176.6 29.07 180 top
CH203  0.1U_0402_10V6K  [C_0402]  170.95 28.13 270 top
CH204  1U_0402_6.3V6K  [C_0402]  123.42 94.57 180 top
CI9  0.1U_0402_10V6K  [C_0402]  286.45 51.55 0 bottom
CI10  0.1U_0402_10V6K  [C_0402]  286.45 50.66 0 bottom
CI11  47U_0805_6.3V6M  [C_0805]  293.75 42.94 180 bottom
CI12  10U_0603_6.3V6M  [C_0603]  293.55 46.52 180 bottom
CI13  0.1U_0402_10V6K  [C_0402]  293.33 47.97 180 bottom
CI16  0.1U_0402_10V6K  [C_0402]  283.14 32.38 0 bottom
CI17  47U_0805_6.3V6M  [C_0805]  292.87 27.6 180 top
CI18  10U_0603_6.3V6M  [C_0603]  292.63 26.08 180 top
CI19  0.1U_0402_10V6K  [C_0402]  293.58 26.25 270 top
CI20  0.1U_0402_10V6K  [C_0402]  283.14 31.49 0 bottom
CI23  0.1U_0402_10V6K  [C_0402]  279.08 36.85 180 top
CI24  1U_0402_6.3V6K  [C_0402]  292.14 34.08 0 top
CL15  0.1U_0402_10V6K  [C_0402]  289.62 46.09 0 bottom
CL19  0.1U_0402_10V6K  [C_0402]  282.95 50.28 0 bottom
CL20  0.1U_0402_10V6K  [C_0402]  285.58 46.79 180 top
CL21  0.1U_0402_10V6K  [C_0402]  283.98 42.71 90 top
CL22  0.1U_0402_10V6K  [C_0402]  287.42 46.79 180 top
CL24  0.1U_0402_10V6K  [C_0402]  282.46 40.71 270 bottom
CL30  0.1U_0402_10V6K  [C_0402]  288.55 39.79 90 bottom
CL31  0.1U_0402_10V6K  [C_0402]  287.66 39.79 90 bottom
CL32  0.1U_0402_10V6K  [C_0402]  283.98 45.53 270 top
CL33  10P_1206_2KV8J  [C_1206]  289.9 96.99 135 bottom
CL34  0.1U_0402_10V6K  [C_0402]  285.25 40.66 270 bottom
CL35  1U_0402_6.3V6K  [C_0402]  284.36 40.66 270 bottom
CL36  10P_0402_25V8J  [C_0402]  281.82 45 90 bottom
CL37  10P_0402_25V8J  [C_0402]  281.82 44.14 270 bottom
CL39  1U_0402_6.3V6K  [C_0402]  275.8 48.95 180 bottom
CL41  0.01U_0402_16V7K  [C_0402]  294.52 84.01 270 top
CL42  0.1U_0402_10V7K  [C_0402]  283.35 40.71 270 bottom
CL43  4.7U_0402_6.3V6M  [C_0402]  289.62 46.98 0 bottom
CL44  4.7U_0402_6.3V6M  [C_0402]  283.35 47.77 90 top
CL47  0.1U_0402_10V6K  [C_0402]  290.54 44.69 180 bottom
CL48  0.1U_0402_10V6K  [C_0402]  290.54 43.81 180 bottom
CLRP1  SHORT PADS  [SHORTPADS]  176.29 14.21 180 bottom
CM1  0.47U_0402_6.3V6K  [C_0402]  270.09 29.33 180 bottom
CM2  10U_0603_6.3V6M  [C_0603]  268.68 31.87 0 bottom
CM3  0.1U_0402_10V6K  [C_0402]  262.47 32.88 180 bottom
CM4  0.1U_0402_10V6K  [C_0402]  267.42 34.92 180 bottom
CM5  0.1U_0402_10V6K  [C_0402]  268.67 33.01 0 bottom
CM6  0.1U_0201_6.3V6K  [C_0201]  261.29 37.84 180 top
CM7  0.1U_0201_6.3V6K  [C_0201]  261.29 37.2 180 top
CM8  0.47U_0402_6.3V6K  [C_0402]  274.15 37.46 180 bottom
CM9  10U_0603_6.3V6M  [C_0603]  271.79 39.04 270 bottom
CM10  0.1U_0402_10V6K  [C_0402]  266.02 38.55 90 bottom
CM11  0.01U_0402_16V7K  [C_0402]  266.66 35.93 180 bottom
CM12  0.1U_0402_10V6K  [C_0402]  265.14 37.33 180 bottom
CM13  0.01U_0402_16V7K  [C_0402]  267.04 38.55 90 bottom
CM14  0.1U_0201_6.3V6K  [C_0201]  261.29 36.19 180 top
CM15  0.1U_0201_6.3V6K  [C_0201]  261.29 35.55 180 top
CM16  0.1U_0201_6.3V6K  [C_0201]  261.29 34.53 180 top
CM17  0.1U_0201_6.3V6K  [C_0201]  261.29 33.9 180 top
CM18  0.1U_0201_6.3V6K  [C_0201]  261.29 32.88 180 top
CM19  0.1U_0201_6.3V6K  [C_0201]  261.29 32.25 180 top
CM20  0.1U_0201_6.3V6K  [C_0201]  262.15 40.27 180 top
CM21  0.1U_0201_6.3V6K  [C_0201]  262.15 40.85 180 top
CM22  0.47U_0402_6.3V6K  [C_0402]  263.15 29.38 90 bottom
CM23  10U_0603_6.3V6M  [C_0603]  265.69 30.66 270 bottom
CM24  0.1U_0402_10V6K  [C_0402]  266.84 30.67 270 bottom
CM25  0.01U_0402_16V7K  [C_0402]  267.73 30.67 270 bottom
CM26  0.47U_0402_6.3V6K  [C_0402]  261.36 42.41 0 bottom
CM27  10U_0603_6.3V6M  [C_0603]  262.58 39.49 180 bottom
CM28  0.1U_0402_10V6K  [C_0402]  262.47 37.46 180 bottom
CM29  0.1U_0402_10V6K  [C_0402]  262.47 33.9 180 bottom
CM30  0.1U_0402_10V6K  [C_0402]  262.47 38.34 180 bottom
CM31  0.01U_0402_16V7K  [C_0402]  262.47 35.68 180 bottom
CM32  0.01U_0402_16V7K  [C_0402]  262.47 36.57 180 bottom
CM33  0.01U_0402_16V7K  [C_0402]  262.47 34.79 180 bottom
CM34  10U_0603_6.3V6M  [C_0603]  271.79 36.12 270 bottom
CM35  0.1U_0402_10V6K  [C_0402]  268.74 36.74 90 bottom
CM36  0.01U_0402_16V7K  [C_0402]  269.63 34.99 270 bottom
CM37  0.47U_0402_6.3V6K  [C_0402]  274.15 34.92 180 bottom
CM38  0.1U_0402_10V6K  [C_0402]  268.74 34.99 270 bottom
CM39  0.01U_0402_16V7K  [C_0402]  269.63 36.74 90 bottom
CM40  0.1U_0402_10V6K  [C_0402]  270.01 28.64 270 top
CM41  1U_0402_6.3V6K  [C_0402]  263.79 39.03 90 bottom
CM43  12P_0402_50V8J  [C_0402]  266.53 40 180 top
CM44  15P_0402_50V8J  [C_0402]  267.52 40 0 top
CM45  0.1U_0201_6.3V6K  [C_0201]  260.97 40.27 180 top
CM46  0.1U_0201_6.3V6K  [C_0201]  260.97 40.85 180 top
CN1  22U_0603_6.3V6M  [C_0603]  200.99 25.9 180 top
CN2  .1U_0402_16V7K  [C_0402]  200.82 26.94 180 top
CN6  22U_0603_6.3V6M  [C_0603]  184.44 29.19 90 top
CN7  .1U_0402_16V7K  [C_0402]  185.51 29.15 90 top
CN8  .1U_0402_16V7K  [C_0402]  198.74 31.94 0 top
CN9  1000P_0402_50V7K  [C_0402]  201.25 28.92 90 top
CN20  0.1U_0402_10V7K  [C_0402]  191.14 35.88 270 bottom
CN21  0.1U_0402_10V7K  [C_0402]  190.26 35.88 270 bottom
CS12  1000P_0402_50V7K  [C_0402]  199.15 18.58 90 bottom
CS13  0.1U_0402_10V6K  [C_0402]  200.03 18.58 90 bottom
CS14  1U_0402_6.3V6K  [C_0402]  200.92 18.58 90 bottom
CS15  10U_0603_6.3V6M  [C_0603]  202.07 18.09 90 bottom
CS25  0.01U_0402_16V7K  [C_0402]  192.22 17.08 270 top
CS26  0.01U_0402_16V7K  [C_0402]  193.11 17.08 270 top
CS27  0.01U_0402_16V7K  [C_0402]  191.25 17.08 270 top
CS28  0.01U_0402_16V7K  [C_0402]  190.37 17.08 270 top
CT79  22P_0402_50V8J  [C_0402]  149.86 18.79 0 bottom
CT80  0.01U_0402_16V7K  [C_0402]  108.06 84.85 0 top
CT81  0.1U_0201_10V6K  [C_0201]  60.68 50.92 0 bottom
CT82  2200P_0402_25V7K  [C_0402]  63.76 49.98 270 bottom
CT83  2200P_0402_25V7K  [C_0402]  146.44 80.33 270 top
CT84  2200P_0402_25V7K  [C_0402]  212.88 14.36 90 bottom
CT85  2200P_0402_25V7K  [C_0402]  63.76 48.2 270 bottom
CV50  47U_0805_6.3V6M  [C_0805]  158.85 78.77 270 top
CV51  10U_0603_6.3V6M  [C_0603]  160.33 79.4 270 top
CV52  0.1U_0402_10V7K  [C_0402]  159.31 79.81 180 top
CV53  0.1U_0402_10V7K  [C_0402]  160.81 80.92 180 top
CV70  10P_0402_50V8J  [C_0402]  176.28 72.86 0 bottom
CV71  10P_0402_50V8J  [C_0402]  178.92 72.86 180 bottom
CV72  0.1U_0402_10V7K  [C_0402]  163.3 82.32 0 top
CV73  22U_0805_6.3V6M  [C_0805]  163.41 80.92 0 top
CV74  4.7U_0603_6.3V6K  [C_0603]  158.94 127.91 180 top
CV75  4.7U_0603_6.3V6K  [C_0603]  178.91 106.23 270 top
CV76  4.7U_0603_6.3V6K  [C_0603]  182.96 91.52 90 top
CV77  4.7U_0603_6.3V6K  [C_0603]  181.15 97.49 90 top
CV78  4.7U_0603_6.3V6K  [C_0603]  174.8 85.64 90 top
CV79  10U_0603_6.3V6M  [C_0603]  154.51 123.56 0 top
CV80  10U_0603_6.3V6M  [C_0603]  174.81 84.59 270 top
CV83  22U_0805_6.3V6M  [C_0805]  185.05 83.66 270 top
CV84  22U_0805_6.3V6M  [C_0805]  183.3 83.66 270 top
CV85  22U_0805_6.3V6M  [C_0805]  181.56 83.67 270 top
CV86  22U_0805_6.3V6M  [C_0805]  174.55 116.83 0 top
CV87  1U_0402_6.3V6K  [C_0402]  159.95 97.12 0 top
CV88  1U_0402_6.3V6K  [C_0402]  161.86 89.32 0 top
CV89  1U_0402_6.3V6K  [C_0402]  161.81 93.99 0 top
CV90  1U_0402_6.3V6K  [C_0402]  161.81 93.11 0 top
CV91  4.7U_0603_6.3V6K  [C_0603]  156.32 108.86 0 top
CV92  4.7U_0603_6.3V6K  [C_0603]  159.12 101.87 0 top
CV93  10U_0603_6.3V6M  [C_0603]  157.72 107.59 180 top
CV94  10U_0603_6.3V6M  [C_0603]  162.48 90.51 90 top
CV95  10U_0603_6.3V6M  [C_0603]  157.72 106.32 180 top
CV96  22U_0805_6.3V6M  [C_0805]  154.06 104.16 180 top
CV97  22U_0805_6.3V6M  [C_0805]  154.01 105.91 180 top
CV98  22U_0805_6.3V6M  [C_0805]  154.06 100.6 180 top
CV99  22U_0805_6.3V6M  [C_0805]  154.06 102.38 180 top
CV100  1U_0402_6.3V6K  [C_0402]  175.77 92.15 0 top
CV101  1U_0402_6.3V6K  [C_0402]  168.57 100.55 90 top
CV102  1U_0402_6.3V6K  [C_0402]  177.87 105.71 270 top
CV103  1U_0402_6.3V6K  [C_0402]  170.26 96.67 180 top
CV104  0.1U_0402_10V7K  [C_0402]  182.12 105.4 0 top
CV105  0.1U_0402_10V7K  [C_0402]  182.12 104.51 0 top
CV106  0.1U_0402_10V7K  [C_0402]  181.51 101.63 0 top
CV107  0.1U_0402_10V7K  [C_0402]  181.17 103.41 90 top
CV108  0.1U_0402_10V7K  [C_0402]  181.51 102.52 0 top
CV109  0.1U_0402_10V7K  [C_0402]  155.97 121.33 90 top
CV110  4.7U_0603_6.3V6K  [C_0603]  176.35 130.47 90 top
CV111  10U_0603_6.3V6M  [C_0603]  160.97 98.16 180 top
CV112  1U_0402_6.3V6K  [C_0402]  176.03 84.95 270 top
CV113  1U_0402_6.3V6K  [C_0402]  170.23 102.86 0 top
CV114  0.1U_0402_10V7K  [C_0402]  161.77 86.38 0 top
CV115  4.7U_0603_6.3V6K  [C_0603]  157.68 82.19 270 top
CV116  4.7U_0603_6.3V6K  [C_0603]  158.88 82.19 270 top
CV117  0.1U_0402_10V7K  [C_0402]  170.9 81.47 90 top
CV118  0.1U_0402_10V7K  [C_0402]  172.69 81.45 90 top
CV119  1U_0402_6.3V6K  [C_0402]  171.8 81.45 90 top
CV120  4.7U_0603_6.3V6K  [C_0603]  171.9 78.1 180 top
CV121  0.1U_0402_10V7K  [C_0402]  161.86 88.43 0 top
CV122  1U_0603_10V6K  [C_0603]  159.12 103.14 0 top
CV123  4.7U_0805_25V6-K  [C_0805]  156.3 104.79 0 top
CV151  22U_0805_6.3V6M~D  [C_0805]  149.01 106.04 0 bottom
CV152  0.1U_0402_10V7K  [C_0402]  174.64 96.57 180 top
CV153  0.1U_0402_10V7K  [C_0402]  176.02 89.86 270 top
CV154  0.1U_0402_10V7K  [C_0402]  168.4 97.6 270 top
CV155  1U_0402_6.3V6K  [C_0402]  149.41 100.32 0 bottom
CV156  22U_0805_6.3V6M  [C_0805]  149.02 101.72 0 bottom
CV158  820P_0402_25V7  [C_0402]  171.69 130.56 90 top
CV159  820P_0402_25V7  [C_0402]  168.97 130.54 90 top
CV160  10U_0603_6.3V6M  [C_0603]  174.1 131.84 270 top
CV161  1U_0603_25V6  [C_0603]  181.4 130.47 90 top
CV162  1U_0603_25V6  [C_0603]  161.53 131.2 90 top
CV163  1U_0603_25V6  [C_0603]  162.93 131.2 90 top
CV164  1U_0603_25V6  [C_0603]  166.17 132.23 180 top
CV165  0.1U_0402_10V7K  [C_0402]  181.67 119.23 0 top
CV166  0.1U_0402_10V7K  [C_0402]  175.27 121.22 270 top
CV167  0.1U_0402_10V7K  [C_0402]  163.79 127.38 90 top
CV168  10U_0603_6.3V6M  [C_0603]  196.61 82.48 90 top
CV169  1U_0603_25V6  [C_0603]  180.1 130.46 90 top
CV170  1U_0603_25V6  [C_0603]  205.57 88.94 0 top
CV171  1U_0603_25V6  [C_0603]  199.69 95.73 0 top
CV172  1U_0603_25V6  [C_0603]  200.82 102.17 180 top
CV173  0.1U_0402_10V7K  [C_0402]  176.98 105.71 270 top
CV174  0.1U_0402_10V7K  [C_0402]  179.6 102.37 0 top
CV175  0.1U_0402_10V7K  [C_0402]  180.28 103.39 90 top
CV177  820P_0402_25V7  [C_0402]  206.16 93.78 0 top
CV178  820P_0402_25V7  [C_0402]  206.19 92.85 0 top
CV179  10U_0603_6.3V6M  [C_0603]  202.5 83.63 180 top
CV180  1U_0603_25V6  [C_0603]  207.45 82.87 0 top
CV181  1U_0603_25V6  [C_0603]  206.94 80.84 0 top
CV182  1U_0603_25V6  [C_0603]  207.7 77.35 0 top
CV183  1U_0603_25V6  [C_0603]  208.42 102.88 180 top
CV184  0.1U_0402_10V7K  [C_0402]  200.35 88.71 180 top
CV185  0.1U_0402_10V7K  [C_0402]  198.57 88.71 180 top
CV186  0.1U_0402_10V7K  [C_0402]  169.88 100.51 90 top
CV187  10U_0603_6.3V6M  [C_0603]  194.68 80.8 0 top
CV188  1U_0603_25V6  [C_0603]  196.61 86.29 270 top
CV189  1U_0603_25V6  [C_0603]  196.09 78.32 180 top
CV190  1U_0603_25V6  [C_0603]  179.57 94.76 0 top
CV191  1U_0603_25V6  [C_0603]  196.09 79.56 180 top
CV192  0.1U_0402_10V7K  [C_0402]  167.53 103.59 315 top
CV193  0.1U_0402_10V7K  [C_0402]  171.99 96.72 180 top
CV194  0.1U_0402_10V7K  [C_0402]  163.29 103.19 180 top
CV202  0.1U_0402_10V7K  [C_0402]  161.77 85.49 0 top
CV203  0.1U_0402_10V7K  [C_0402]  163.29 102.31 180 top
CV204  0.1U_0402_10V7K  [C_0402]  162.62 96.7 180 top
CV205  0.1U_0402_10V7K  [C_0402]  164.43 96.67 180 top
CV206  0.1U_0402_10V7K  [C_0402]  165.82 98.07 180 top
CV207  0.1U_0402_10V7K  [C_0402]  155.97 120.08 270 top
CV208  0.1U_0402_10V7K  [C_0402]  199.35 83.05 180 top
CV209  0.1U_0402_10V7K  [C_0402]  176.13 94.12 45 top
CV210  1U_0402_6.3V6K  [C_0402]  163.12 104.59 180 top
CV211  1U_0402_6.3V6K  [C_0402]  165.33 96.68 0 top
CV212  0.1U_0402_10V7K  [C_0402]  145.29 76.24 90 bottom
CV213  4.7U_0603_6.3V6K  [C_0603]  176.01 78.12 0 top
CV214  1U_0402_6.3V6K  [C_0402]  175.17 81.82 180 top
CV215  0.1U_0402_10V7K  [C_0402]  160.16 121.86 270 top
CV373  10U_0603_6.3V6M  [C_0603]  159.4 106.29 0 top
CV374  0.1U_0402_10V7K  [C_0402]  178.35 89.71 180 top
CV375  0.1U_0402_10V7K  [C_0402]  180.91 87.51 270 top
CV376  0.1U_0402_10V7K  [C_0402]  180.17 89.72 315 top
CV377  0.1U_0402_10V7K  [C_0402]  176.65 82.46 270 top
CV378  0.1U_0402_10V7K  [C_0402]  176.73 87.09 270 top
CV379  0.1U_0402_10V7K  [C_0402]  175.84 86.18 90 top
CV380  0.1U_0402_10V7K  [C_0402]  183.21 128.11 90 top
CV381  10U_0603_6.3V6M  [C_0603]  183.02 106.48 180 top
CV382  0.1U_0402_10V7K  [C_0402]  175.78 127.93 90 top
CV383  0.1U_0402_10V7K  [C_0402]  181.67 120.47 0 top
CV384  0.1U_0402_10V7K  [C_0402]  160.69 122.84 90 top
CV385  0.1U_0402_10V7K  [C_0402]  178.14 117.34 180 top
CV386  0.1U_0402_10V7K  [C_0402]  162.15 124.26 270 top
CV387  0.1U_0402_10V7K  [C_0402]  205.77 96.64 0 top
CV388  0.1U_0402_10V7K  [C_0402]  207.11 99.24 180 top
CV389  10U_0603_6.3V6M  [C_0603]  159.39 105.06 0 top
CV390  0.1U_0402_10V7K  [C_0402]  207.54 86.21 0 top
CV391  0.1U_0402_10V7K  [C_0402]  207.35 84.43 90 top
CV392  0.1U_0402_10V7K  [C_0402]  206.68 87.11 0 top
CV393  0.1U_0402_10V7K  [C_0402]  201.05 107.72 270 top
CV394  0.1U_0402_10V7K  [C_0402]  201.99 76.83 0 top
CV395  0.1U_0402_10V7K  [C_0402]  201.02 99.74 0 top
CV396  0.1U_0402_10V7K  [C_0402]  201.06 75.95 90 top
CV397  10U_0603_6.3V6M  [C_0603]  180.1 81.49 90 top
CV398  0.1U_0402_10V7K  [C_0402]  199.46 107.72 270 top
CV399  0.1U_0402_10V7K  [C_0402]  197.86 107.72 270 top
CV400  0.1U_0402_10V7K  [C_0402]  198.75 95.93 180 top
CV401  0.1U_0402_10V7K  [C_0402]  200.3 94.13 270 top
CV402  0.1U_0402_10V7K  [C_0402]  204.15 81.63 0 top
CV403  0.1U_0402_10V7K  [C_0402]  199.3 75.92 90 top
CV404  0.1U_0402_10V7K  [C_0402]  197.03 77.64 270 top
CV531  0.22U_0201_6.3V6M  [C_0201]  151.47 83.46 180 top
CV532  0.22U_0201_6.3V6M  [C_0201]  151.47 82.82 180 top
CV533  0.22U_0201_6.3V6M  [C_0201]  153.12 84.47 180 top
CV534  0.22U_0201_6.3V6M  [C_0201]  153.12 83.84 180 top
CV535  0.22U_0201_6.3V6M  [C_0201]  151.47 84.86 180 top
CV536  0.22U_0201_6.3V6M  [C_0201]  151.47 85.49 180 top
CV537  0.22U_0201_6.3V6M  [C_0201]  153.12 86.51 180 top
CV538  0.22U_0201_6.3V6M  [C_0201]  153.12 85.87 180 top
CV539  0.22U_0201_6.3V6M  [C_0201]  151.47 86.89 180 top
CV540  0.22U_0201_6.3V6M  [C_0201]  151.47 87.52 180 top
CV541  0.22U_0201_6.3V6M  [C_0201]  153.12 88.54 180 top
CV542  0.22U_0201_6.3V6M  [C_0201]  153.12 87.9 180 top
CV543  0.22U_0201_6.3V6M  [C_0201]  151.47 88.92 180 top
CV544  0.22U_0201_6.3V6M  [C_0201]  151.47 89.55 180 top
CV545  0.22U_0201_6.3V6M  [C_0201]  153.12 90.57 180 top
CV546  0.22U_0201_6.3V6M  [C_0201]  153.12 89.94 180 top
CV547  0.22U_0201_6.3V6M  [C_0201]  151.47 91.59 180 top
CV548  0.22U_0201_6.3V6M  [C_0201]  151.47 90.95 180 top
CV550  0.22U_0201_6.3V6M  [C_0201]  153.12 91.97 180 top
CV551  0.22U_0201_6.3V6M  [C_0201]  153.12 92.6 180 top
CV552  0.22U_0201_6.3V6M  [C_0201]  151.47 93.62 180 top
CV557  0.22U_0201_6.3V6M  [C_0201]  151.47 92.98 180 top
CV558  0.22U_0201_6.3V6M  [C_0201]  153.12 94 180 top
CV559  0.22U_0201_6.3V6M  [C_0201]  153.12 94.63 180 top
CV560  0.22U_0201_6.3V6M  [C_0201]  151.47 95.65 180 top
CV561  0.22U_0201_6.3V6M  [C_0201]  151.47 95.02 180 top
CV562  0.22U_0201_6.3V6M  [C_0201]  153.12 96.03 180 top
